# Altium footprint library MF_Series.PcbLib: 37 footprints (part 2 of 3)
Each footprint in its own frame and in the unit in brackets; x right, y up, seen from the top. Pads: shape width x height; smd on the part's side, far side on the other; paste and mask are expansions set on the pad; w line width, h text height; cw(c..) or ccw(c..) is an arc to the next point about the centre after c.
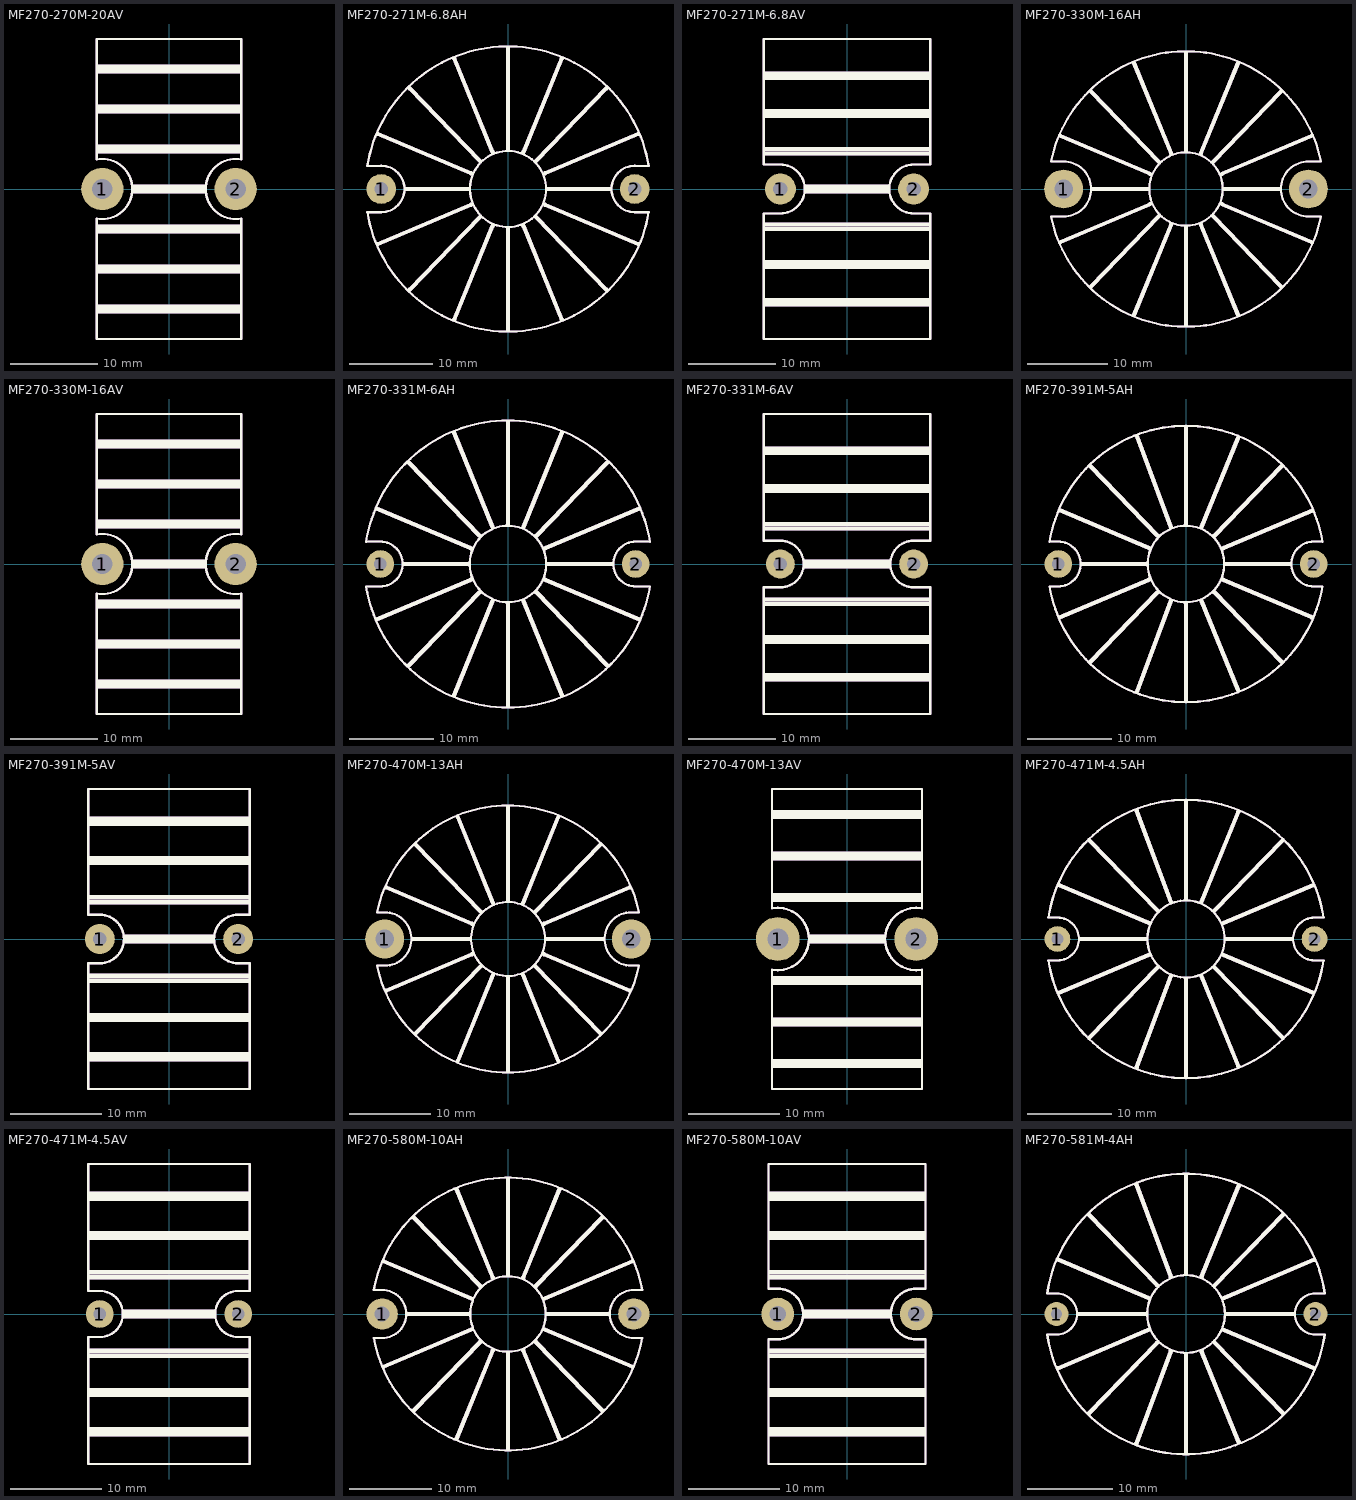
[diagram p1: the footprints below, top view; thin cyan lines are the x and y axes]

## MF270-270M-20AV [mil]
pads (2):
  round 190 hole 91: 1(-300,0) 2(300,0)
Top Overlay:
  lines w10: -325,-132.66 ccw(c-300,0) -325,132.66 ; -325,-132.27 -325,-675 325,-675 325,-132.27 ; -325,132.27 -325,675 325,675 325,132.27 ; 325,-132.66 cw(c300,0) 325,132.66
  lines w19.68: -320,-550 320,-550 ; -320,-530 320,-530 ; -320,-370 320,-370 ; -320,-350 320,-350 ; -320,-190 320,-190 ; -320,-170 320,-170 ; -320,170 320,170 ; -320,190 320,190 ; -320,350 320,350 ; -320,370 320,370 ; -320,530 320,530 ; -320,550 320,550 ; -160,-10 160,-10 ; -160,10 160,10
Mechanical 29:
  lines w10: -325,-132.66 ccw(c-300,0) -325,132.66 ; -325,-132.27 -325,-675 325,-675 325,-132.27 ; -325,132.27 -325,675 325,675 325,132.27 ; 325,-132.66 cw(c300,0) 325,132.66
  lines w19.68: -320,-550 320,-550 ; -320,-530 320,-530 ; -320,-370 320,-370 ; -320,-350 320,-350 ; -320,-190 320,-190 ; -320,-170 320,-170 ; -320,170 320,170 ; -320,190 320,190 ; -320,350 320,350 ; -320,370 320,370 ; -320,530 320,530 ; -320,550 320,550 ; -160,-10 160,-10 ; -160,10 160,10
  text "'.Designator'" at -1750,-64.83 h400

## MF270-271M-6.8AH [mil]
pads (2):
  round 140 hole 65: 1(-600,0) 2(600,0)
Top Overlay:
  circle w10: c0,0 r180
  lines w10: 666.04,109.62 ccw(c0,0) -666.02,109.73 -600,110 cw(c-600,0) -600,-110 -665.98,-110 ccw(c0,0) 665.98,-110 600,-110 cw(c600,0) 600,110 666.04,109.73
  lines w19.68: -617.26,-261.55 -175.3,-74.28 ; -617.26,261.55 -175.3,74.28 ; -485,0 -185,0 ; -466.61,-477.13 -132.5,-132.5 ; -466.61,477.13 -132.5,132.5 ; -254.48,-618.14 -72.46,-173.99 ; -254.48,618.14 -72.46,173.99 ; 0,-665 0,-185 ; 0,185 0,665 ; 72.46,-173.99 254.48,-618.14 ; 72.46,173.99 254.48,618.14 ; 132.5,-132.5 466.61,-477.13 ; 132.5,132.5 466.61,477.13 ; 175.3,-74.28 617.26,-261.55 ; 175.3,74.28 617.26,261.55 ; 185,0 485,0
Mechanical 29:
  circle w10: c0,0 r180
  lines w10: 666.04,109.62 ccw(c0,0) -666.02,109.73 -600,110 cw(c-600,0) -600,-110 -665.98,-110 ccw(c0,0) 665.98,-110 600,-110 cw(c600,0) 600,110 666.04,109.73
  lines w19.68: -617.26,-261.55 -175.3,-74.28 ; -617.26,261.55 -175.3,74.28 ; -485,0 -185,0 ; -466.61,-477.13 -132.5,-132.5 ; -466.61,477.13 -132.5,132.5 ; -254.48,-618.14 -72.46,-173.99 ; -254.48,618.14 -72.46,173.99 ; 0,-665 0,-185 ; 0,185 0,665 ; 72.46,-173.99 254.48,-618.14 ; 72.46,173.99 254.48,618.14 ; 132.5,-132.5 466.61,-477.13 ; 132.5,132.5 466.61,477.13 ; 175.3,-74.28 617.26,-261.55 ; 175.3,74.28 617.26,261.55 ; 185,0 485,0
  text "'.Designator'" at -290,145.17 h400

## MF270-271M-6.8AV [mil]
pads (2):
  round 140 hole 65: 1(-300,0) 2(300,0)
Top Overlay:
  lines w10: -375,-675 375,-675 375,-110 300,-110 cw(c300,0) 300,110 375,110 375,675 -375,675 -375,110 -300,110 cw(c-300,0) -300,-110 -375,-110 -375,-675
  lines w19.68: -370,-520 370,-520 ; -370,-500 370,-500 ; -370,-350 370,-350 ; -370,-330 370,-330 ; -370,-180 370,-180 ; -370,-160 370,-160 ; -370,160 370,160 ; -370,180 370,180 ; -370,330 370,330 ; -370,350 370,350 ; -370,500 370,500 ; -370,520 370,520 ; -185,-10 185,-10 ; -185,10 185,10
Mechanical 29:
  lines w10: -375,-675 375,-675 375,-110 300,-110 cw(c300,0) 300,110 375,110 375,675 -375,675 -375,110 -300,110 cw(c-300,0) -300,-110 -375,-110 -375,-675
  lines w19.68: -370,-520 370,-520 ; -370,-500 370,-500 ; -370,-350 370,-350 ; -370,-330 370,-330 ; -370,-180 370,-180 ; -370,-160 370,-160 ; -370,160 370,160 ; -370,180 370,180 ; -370,330 370,330 ; -370,350 370,350 ; -370,500 370,500 ; -370,520 370,520 ; -185,-10 185,-10 ; -185,10 185,10
  text "'.Designator'" at -1750,-64.83 h400

## MF270-330M-16AH [mil]
pads (2):
  round 190 hole 91: 1(-600,0) 2(600,0)
Top Overlay:
  circle w10: c0,0 r180
  lines w10: -661.36,-135 ccw(c0,0) 661.36,-135 600,-135 cw(c600,0) 600,135 661.36,135 ccw(c0,0) -661.36,135 -600,135 cw(c-600,0) -600,-135 -661.36,-135
  lines w19.68: -617.26,-261.55 -175.3,-74.28 ; -617.26,261.55 -175.3,74.28 ; -466.61,-477.13 -132.5,-132.5 ; -466.61,477.13 -132.5,132.5 ; -460,0 -185,0 ; -254.48,-618.14 -72.46,-173.99 ; -254.48,618.14 -72.46,173.99 ; 0,-665 0,-185 ; 0,185 0,665 ; 72.46,-173.99 254.48,-618.14 ; 72.46,173.99 254.48,618.14 ; 132.5,-132.5 466.61,-477.13 ; 132.5,132.5 466.61,477.13 ; 175.3,-74.28 617.26,-261.55 ; 175.3,74.28 617.26,261.55 ; 185,0 460,0
Mechanical 29:
  circle w10: c0,0 r180
  lines w10: -661.36,-135 ccw(c0,0) 661.36,-135 600,-135 cw(c600,0) 600,135 661.36,135 ccw(c0,0) -661.36,135 -600,135 cw(c-600,0) -600,-135 -661.36,-135
  lines w19.68: -617.26,-261.55 -175.3,-74.28 ; -617.26,261.55 -175.3,74.28 ; -466.61,-477.13 -132.5,-132.5 ; -466.61,477.13 -132.5,132.5 ; -460,0 -185,0 ; -254.48,-618.14 -72.46,-173.99 ; -254.48,618.14 -72.46,173.99 ; 0,-665 0,-185 ; 0,185 0,665 ; 72.46,-173.99 254.48,-618.14 ; 72.46,173.99 254.48,618.14 ; 132.5,-132.5 466.61,-477.13 ; 132.5,132.5 466.61,477.13 ; 175.3,-74.28 617.26,-261.55 ; 175.3,74.28 617.26,261.55 ; 185,0 460,0
  text "'.Designator'" at -290,145.17 h400

## MF270-330M-16AV [mil]
pads (2):
  round 190 hole 91: 1(-300,0) 2(300,0)
Top Overlay:
  lines w10: -325,-132.66 ccw(c-300,0) -325,132.66 ; -325,-132.27 -325,-675 325,-675 325,-132.27 ; -325,132.27 -325,675 325,675 325,132.27 ; 325,-132.66 cw(c300,0) 325,132.66
  lines w19.68: -320,-550 320,-550 ; -320,-530 320,-530 ; -320,-370 320,-370 ; -320,-350 320,-350 ; -320,-190 320,-190 ; -320,-170 320,-170 ; -320,170 320,170 ; -320,190 320,190 ; -320,350 320,350 ; -320,370 320,370 ; -320,530 320,530 ; -320,550 320,550 ; -160,-10 160,-10 ; -160,10 160,10
Mechanical 29:
  lines w10: -325,-132.66 ccw(c-300,0) -325,132.66 ; -325,-132.27 -325,-675 325,-675 325,-132.27 ; -325,132.27 -325,675 325,675 325,132.27 ; 325,-132.66 cw(c300,0) 325,132.66
  lines w19.68: -320,-550 320,-550 ; -320,-530 320,-530 ; -320,-370 320,-370 ; -320,-350 320,-350 ; -320,-190 320,-190 ; -320,-170 320,-170 ; -320,170 320,170 ; -320,190 320,190 ; -320,350 320,350 ; -320,370 320,370 ; -320,530 320,530 ; -320,550 320,550 ; -160,-10 160,-10 ; -160,10 160,10
  text "'.Designator'" at -1750,-64.83 h400

## MF270-331M-6AH [mil]
pads (2):
  round 130 hole 60: 1(-600,0) 2(600,0)
Top Overlay:
  circle w10: c0,0 r180
  lines w10: -666.81,104.84 cw(c0,0) 666.82,104.75 ; -666.77,-105.1 ccw(c0,0) 666.78,-105.02 ; -666.13,-105 -600,-105 ccw(c-600,0) -600,105 -666.15,104.73 ; 666.67,-105 600,-105 cw(c600,0) 600,105 666.7,104.73
  lines w19.68: -617.26,-261.55 -175.3,-74.28 ; -617.26,261.55 -175.3,74.28 ; -490,0 -185,0 ; -466.61,-477.13 -132.5,-132.5 ; -466.61,477.13 -132.5,132.5 ; -254.48,-618.14 -72.46,-173.99 ; -254.48,618.14 -72.46,173.99 ; 0,-665 0,-185 ; 0,185 0,665 ; 72.46,-173.99 254.48,-618.14 ; 72.46,173.99 254.48,618.14 ; 132.5,-132.5 466.61,-477.13 ; 132.5,132.5 466.61,477.13 ; 175.3,-74.28 617.26,-261.55 ; 175.3,74.28 617.26,261.55 ; 185,0 490,0
Mechanical 29:
  circle w10: c0,0 r180
  lines w10: -666.81,104.84 cw(c0,0) 666.82,104.75 ; -666.77,-105.1 ccw(c0,0) 666.78,-105.02 ; -666.13,-105 -600,-105 ccw(c-600,0) -600,105 -666.15,104.73 ; 666.67,-105 600,-105 cw(c600,0) 600,105 666.7,104.73
  lines w19.68: -617.26,-261.55 -175.3,-74.28 ; -617.26,261.55 -175.3,74.28 ; -490,0 -185,0 ; -466.61,-477.13 -132.5,-132.5 ; -466.61,477.13 -132.5,132.5 ; -254.48,-618.14 -72.46,-173.99 ; -254.48,618.14 -72.46,173.99 ; 0,-665 0,-185 ; 0,185 0,665 ; 72.46,-173.99 254.48,-618.14 ; 72.46,173.99 254.48,618.14 ; 132.5,-132.5 466.61,-477.13 ; 132.5,132.5 466.61,477.13 ; 175.3,-74.28 617.26,-261.55 ; 175.3,74.28 617.26,261.55 ; 185,0 490,0
  text "'.Designator'" at -290,145.17 h400

## MF270-331M-6AV [mil]
pads (2):
  round 130 hole 60: 1(-300,0) 2(300,0)
Top Overlay:
  lines w10: -375,-675 375,-675 375,-105 300,-105 cw(c300,0) 300,105 375,105 375,675 -375,675 -375,105 -300,105 cw(c-300,0) -300,-105 -375,-105 -375,-675
  lines w19.68: -370,-520 370,-520 ; -370,-500 370,-500 ; -370,-350 370,-350 ; -370,-330 370,-330 ; -370,-180 370,-180 ; -370,-160 370,-160 ; -370,160 370,160 ; -370,180 370,180 ; -370,330 370,330 ; -370,350 370,350 ; -370,500 370,500 ; -370,520 370,520 ; -190,-10 190,-10 ; -190,10 190,10
Mechanical 29:
  lines w10: -375,-675 375,-675 375,-105 300,-105 cw(c300,0) 300,105 375,105 375,675 -375,675 -375,105 -300,105 cw(c-300,0) -300,-105 -375,-105 -375,-675
  lines w19.68: -370,-520 370,-520 ; -370,-500 370,-500 ; -370,-350 370,-350 ; -370,-330 370,-330 ; -370,-180 370,-180 ; -370,-160 370,-160 ; -370,160 370,160 ; -370,180 370,180 ; -370,330 370,330 ; -370,350 370,350 ; -370,500 370,500 ; -370,520 370,520 ; -190,-10 190,-10 ; -190,10 190,10
  text "'.Designator'" at -1750,-64.83 h400

## MF270-391M-5AH [mil]
pads (2):
  round 130 hole 60: 1(-600,0) 2(600,0)
Top Overlay:
  circle w10: c0,0 r180
  lines w10: -641.49,104.83 cw(c0,0) 641.49,104.83 600,105 ccw(c600,0) 600,-105 641.46,-105 cw(c0,0) -641.46,-105 -600,-105 ccw(c-600,0) -600,105 -641.49,104.83
  lines w19.68: -594.24,-251.8 -175.3,-74.28 ; -593.79,252.95 -173.05,74.68 ; -490,0 -185,0 ; -450,-460 -132.7,-132.43 ; -450,460 -132.7,132.43 ; -230,-600 -70.44,-171.87 ; -230,600 -70.44,171.87 ; 0,-640 0,-185 ; 0,185 0,640 ; 72.46,-173.99 243.97,-592.47 ; 72.46,173.99 243.97,592.47 ; 132.5,-132.5 450,-460 ; 132.5,132.5 450,460 ; 175.3,-74.28 590,-250 ; 175.3,74.28 594.24,251.8 ; 185,0 490,0
Mechanical 29:
  circle w10: c0,0 r180
  lines w10: -641.49,104.83 cw(c0,0) 641.49,104.83 600,105 ccw(c600,0) 600,-105 641.46,-105 cw(c0,0) -641.46,-105 -600,-105 ccw(c-600,0) -600,105 -641.49,104.83
  lines w19.68: -594.24,-251.8 -175.3,-74.28 ; -593.79,252.95 -173.05,74.68 ; -490,0 -185,0 ; -450,-460 -132.7,-132.43 ; -450,460 -132.7,132.43 ; -230,-600 -70.44,-171.87 ; -230,600 -70.44,171.87 ; 0,-640 0,-185 ; 0,185 0,640 ; 72.46,-173.99 243.97,-592.47 ; 72.46,173.99 243.97,592.47 ; 132.5,-132.5 450,-460 ; 132.5,132.5 450,460 ; 175.3,-74.28 590,-250 ; 175.3,74.28 594.24,251.8 ; 185,0 490,0
  text "'.Designator'" at -290,145.17 h400

## MF270-391M-5AV [mil]
pads (2):
  round 130 hole 60: 1(-300,0) 2(300,0)
Top Overlay:
  lines w10: -350,-650 -350,-105 -300,-105 ccw(c-300,0) -300,105 -350,105 -350,650 350,650 350,105 300,105 ccw(c300,0) 300,-105 350,-105 350,-650 -350,-650
  lines w19.68: -345,-520 345,-520 ; -345,-500 345,-500 ; -345,-350 345,-350 ; -345,-330 345,-330 ; -345,-180 345,-180 ; -345,-160 345,-160 ; -345,160 345,160 ; -345,180 345,180 ; -345,330 345,330 ; -345,350 345,350 ; -345,500 345,500 ; -345,520 345,520 ; -190,-10 190,-10 ; -190,10 190,10
Mechanical 29:
  lines w10: -350,-650 -350,-105 -300,-105 ccw(c-300,0) -300,105 -350,105 -350,650 350,650 350,105 300,105 ccw(c300,0) 300,-105 350,-105 350,-650 -350,-650
  lines w19.68: -345,-520 345,-520 ; -345,-500 345,-500 ; -345,-350 345,-350 ; -345,-330 345,-330 ; -345,-180 345,-180 ; -345,-160 345,-160 ; -345,160 345,160 ; -345,180 345,180 ; -345,330 345,330 ; -345,350 345,350 ; -345,500 345,500 ; -345,520 345,520 ; -190,-10 190,-10 ; -190,10 190,10
  text "'.Designator'" at -1750,-64.83 h400

## MF270-470M-13AH [mil]
pads (2):
  round 190 hole 91: 1(-600,0) 2(600,0)
Top Overlay:
  circle w10: c0,0 r180
  lines w10: -636.85,-130.09 ccw(c0,0) 636.85,-130.09 ; -636.85,130.09 cw(c0,0) 636.79,130.37 ; -636.43,-130 -600,-130 ccw(c-600,0) -600,130 -636.43,130 ; 636.43,-130 600,-130 cw(c600,0) 600,130 636.43,130
  lines w19.68: -594.25,-251.8 -175.3,-74.28 ; -594.25,251.8 -175.3,74.28 ; -465,0 -185,0 ; -449.21,-459.18 -132.5,-132.5 ; -449.21,459.18 -132.5,132.5 ; -245,-595.01 -72.46,-173.99 ; -245,595.01 -72.46,173.99 ; 0,-645 0,-185 ; 0,185 0,645 ; 72.46,-173.99 245,-595.01 ; 72.46,173.99 245,595.01 ; 132.5,-132.5 449.21,-459.18 ; 132.5,132.5 449.21,459.18 ; 175.3,-74.28 594.25,-251.8 ; 175.3,74.28 594.25,251.8 ; 185,0 465,0
Mechanical 29:
  circle w10: c0,0 r180
  lines w10: -636.85,-130.09 ccw(c0,0) 636.85,-130.09 ; -636.85,130.09 cw(c0,0) 636.79,130.37 ; -636.43,-130 -600,-130 ccw(c-600,0) -600,130 -636.43,130 ; 636.43,-130 600,-130 cw(c600,0) 600,130 636.43,130
  lines w19.68: -594.25,-251.8 -175.3,-74.28 ; -594.25,251.8 -175.3,74.28 ; -465,0 -185,0 ; -449.21,-459.18 -132.5,-132.5 ; -449.21,459.18 -132.5,132.5 ; -245,-595.01 -72.46,-173.99 ; -245,595.01 -72.46,173.99 ; 0,-645 0,-185 ; 0,185 0,645 ; 72.46,-173.99 245,-595.01 ; 72.46,173.99 245,595.01 ; 132.5,-132.5 449.21,-459.18 ; 132.5,132.5 449.21,459.18 ; 175.3,-74.28 594.25,-251.8 ; 175.3,74.28 594.25,251.8 ; 185,0 465,0
  text "'.Designator'" at -290,145.17 h400

## MF270-470M-13AV [mil]
pads (2):
  round 190 hole 91: 1(-300,0) 2(300,0)
Top Overlay:
  lines w10: -325,-132.66 ccw(c-300,0) -325,132.66 ; -325,-132.27 -325,-650 325,-650 325,-132.27 ; -325,132.27 -325,650 325,650 325,132.27 ; 325,-132.66 cw(c300,0) 325,132.66
  lines w19.68: -320,-550 320,-550 ; -320,-530 320,-530 ; -320,-370 320,-370 ; -320,-350 320,-350 ; -320,-190 320,-190 ; -320,-170 320,-170 ; -320,170 320,170 ; -320,190 320,190 ; -320,350 320,350 ; -320,370 320,370 ; -320,530 320,530 ; -320,550 320,550 ; -160,-10 160,-10 ; -160,10 160,10
Mechanical 29:
  lines w10: -325,-132.66 ccw(c-300,0) -325,132.66 ; -325,-132.27 -325,-650 325,-650 325,-132.27 ; -325,132.27 -325,650 325,650 325,132.27 ; 325,-132.66 cw(c300,0) 325,132.66
  lines w19.68: -320,-550 320,-550 ; -320,-530 320,-530 ; -320,-370 320,-370 ; -320,-350 320,-350 ; -320,-190 320,-190 ; -320,-170 320,-170 ; -320,170 320,170 ; -320,190 320,190 ; -320,350 320,350 ; -320,370 320,370 ; -320,530 320,530 ; -320,550 320,550 ; -160,-10 160,-10 ; -160,10 160,10
  text "'.Designator'" at -1750,-64.83 h400

## MF270-471M-4.5AH [mil]
pads (2):
  round 120 hole 55: 1(-600,0) 2(600,0)
Top Overlay:
  circle w10: c0,0 r180
  lines w10: -642.52,-100 -600,-100 ccw(c-600,0) -600,100 -642.52,100 ; -642.26,-100 ccw(c0,0) 642.27,-99.96 ; -642.26,100 cw(c0,0) 642.27,99.96 ; 642.52,-100 600,-100 cw(c600,0) 600,100 642.52,100
  lines w19.68: -594.24,-251.8 -175.3,-74.28 ; -593.79,252.95 -173.05,74.68 ; -495,0 -185,0 ; -450,-460 -132.7,-132.43 ; -450,460 -132.7,132.43 ; -230,-600 -70.44,-171.87 ; -230,600 -70.44,171.87 ; 0,-640 0,-185 ; 0,185 0,640 ; 72.46,-173.99 243.97,-592.47 ; 72.46,173.99 243.97,592.47 ; 132.5,-132.5 450,-460 ; 132.5,132.5 450,460 ; 175.3,-74.28 590,-250 ; 175.3,74.28 594.24,251.8 ; 185,0 495,0
Mechanical 29:
  circle w10: c0,0 r180
  lines w10: -642.52,-100 -600,-100 ccw(c-600,0) -600,100 -642.52,100 ; -642.26,-100 ccw(c0,0) 642.27,-99.96 ; -642.26,100 cw(c0,0) 642.27,99.96 ; 642.52,-100 600,-100 cw(c600,0) 600,100 642.52,100
  lines w19.68: -594.24,-251.8 -175.3,-74.28 ; -593.79,252.95 -173.05,74.68 ; -495,0 -185,0 ; -450,-460 -132.7,-132.43 ; -450,460 -132.7,132.43 ; -230,-600 -70.44,-171.87 ; -230,600 -70.44,171.87 ; 0,-640 0,-185 ; 0,185 0,640 ; 72.46,-173.99 243.97,-592.47 ; 72.46,173.99 243.97,592.47 ; 132.5,-132.5 450,-460 ; 132.5,132.5 450,460 ; 175.3,-74.28 590,-250 ; 175.3,74.28 594.24,251.8 ; 185,0 495,0
  text "'.Designator'" at -290,145.17 h400

## MF270-471M-4.5AV [mil]
pads (2):
  round 120 hole 55: 1(-300,0) 2(300,0)
Top Overlay:
  lines w10: -350,-650 -350,-100 -300,-100 ccw(c-300,0) -300,100 -350,100 -350,650 350,650 350,100 300,100 ccw(c300,0) 300,-100 350,-100 350,-650 -350,-650
  lines w19.68: -345,-520 345,-520 ; -345,-500 345,-500 ; -345,-350 345,-350 ; -345,-330 345,-330 ; -345,-180 345,-180 ; -345,-160 345,-160 ; -345,160 345,160 ; -345,180 345,180 ; -345,330 345,330 ; -345,350 345,350 ; -345,500 345,500 ; -345,520 345,520 ; -195,-10 195,-10 ; -195,10 195,10
Mechanical 29:
  lines w10: -350,-650 -350,-100 -300,-100 ccw(c-300,0) -300,100 -350,100 -350,650 350,650 350,100 300,100 ccw(c300,0) 300,-100 350,-100 350,-650 -350,-650
  lines w19.68: -345,-520 345,-520 ; -345,-500 345,-500 ; -345,-350 345,-350 ; -345,-330 345,-330 ; -345,-180 345,-180 ; -345,-160 345,-160 ; -345,160 345,160 ; -345,180 345,180 ; -345,330 345,330 ; -345,350 345,350 ; -345,500 345,500 ; -345,520 345,520 ; -195,-10 195,-10 ; -195,10 195,10
  text "'.Designator'" at -1750,-64.83 h400

## MF270-580M-10AH [mil]
pads (2):
  round 150 hole 71: 1(-600,0) 2(600,0)
Top Overlay:
  circle w10: c0,0 r180
  lines w10: -639.75,-115 ccw(c0,0) 639.75,-115 600,-115 cw(c600,0) 600,115 639.77,114.84 ccw(c0,0) -639.77,114.84 -600,115 cw(c-600,0) -600,-115 -639.75,-115
  lines w19.68: -594.25,-251.8 -175.3,-74.28 ; -594.25,251.8 -175.3,74.28 ; -480,0 -185,0 ; -449.21,-459.18 -132.5,-132.5 ; -449.21,459.18 -132.5,132.5 ; -245,-595.01 -72.46,-173.99 ; -245,595.01 -72.46,173.99 ; 0,-645 0,-185 ; 0,185 0,645 ; 72.46,-173.99 245,-595.01 ; 72.46,173.99 245,595.01 ; 132.5,-132.5 449.21,-459.18 ; 132.5,132.5 449.21,459.18 ; 175.3,-74.28 594.25,-251.8 ; 175.3,74.28 594.25,251.8 ; 185,0 480,0
Mechanical 29:
  circle w10: c0,0 r180
  lines w10: -639.75,-115 ccw(c0,0) 639.75,-115 600,-115 cw(c600,0) 600,115 639.77,114.84 ccw(c0,0) -639.77,114.84 -600,115 cw(c-600,0) -600,-115 -639.75,-115
  lines w19.68: -594.25,-251.8 -175.3,-74.28 ; -594.25,251.8 -175.3,74.28 ; -480,0 -185,0 ; -449.21,-459.18 -132.5,-132.5 ; -449.21,459.18 -132.5,132.5 ; -245,-595.01 -72.46,-173.99 ; -245,595.01 -72.46,173.99 ; 0,-645 0,-185 ; 0,185 0,645 ; 72.46,-173.99 245,-595.01 ; 72.46,173.99 245,595.01 ; 132.5,-132.5 449.21,-459.18 ; 132.5,132.5 449.21,459.18 ; 175.3,-74.28 594.25,-251.8 ; 175.3,74.28 594.25,251.8 ; 185,0 480,0
  text "'.Designator'" at -290,145.17 h400

## MF270-580M-10AV [mil]
pads (2):
  round 142 hole 71: 1(-300,0) 2(300,0)
Top Overlay:
  lines w10: -340,-650 -340,-110 -300,-110 ccw(c-300,0) -300,110 -340,110 -340,650 340,650 340,110 300,110 ccw(c300,0) 300,-110 340,-110 340,-650 -340,-650
  lines w19.68: -335,-520 335,-520 ; -335,-500 335,-500 ; -335,-350 335,-350 ; -335,-330 335,-330 ; -335,-180 335,-180 ; -335,-160 335,-160 ; -335,160 335,160 ; -335,180 335,180 ; -335,330 335,330 ; -335,350 335,350 ; -335,500 335,500 ; -335,520 335,520 ; -185,-10 185,-10 ; -185,10 185,10
Mechanical 29:
  lines w10: -340,-650 -340,-110 -300,-110 ccw(c-300,0) -300,110 -340,110 -340,650 340,650 340,110 300,110 ccw(c300,0) 300,-110 340,-110 340,-650 -340,-650
  lines w19.68: -335,-520 335,-520 ; -335,-500 335,-500 ; -335,-350 335,-350 ; -335,-330 335,-330 ; -335,-180 335,-180 ; -335,-160 335,-160 ; -335,160 335,160 ; -335,180 335,180 ; -335,330 335,330 ; -335,350 335,350 ; -335,500 335,500 ; -335,520 335,520 ; -185,-10 185,-10 ; -185,10 185,10
  text "'.Designator'" at -1750,-64.83 h400

## MF270-581M-4AH [mil]
pads (2):
  round 110 hole 51: 1(-600,0) 2(600,0)
Top Overlay:
  circle w10: c0,0 r180
  lines w10: -643.01,-95.07 ccw(c0,0) 643.06,-94.71 ; -643.01,95.07 cw(c0,0) 642.96,95.44 ; -642.52,-95 -600,-95 ccw(c-600,0) -600,95 -642.52,95 ; 642.52,-95 600,-95 cw(c600,0) 600,95 642.52,95
  lines w19.68: -594.24,-251.8 -175.3,-74.28 ; -593.79,252.95 -173.05,74.68 ; -500,0 -185,0 ; -450,-460 -132.7,-132.43 ; -450,460 -132.7,132.43 ; -230,-600 -70.44,-171.87 ; -230,600 -70.44,171.87 ; 0,-640 0,-185 ; 0,185 0,640 ; 72.46,-173.99 243.97,-592.47 ; 72.46,173.99 243.97,592.47 ; 132.5,-132.5 450,-460 ; 132.5,132.5 450,460 ; 175.3,-74.28 590,-250 ; 175.3,74.28 594.24,251.8 ; 185,0 500,0
Mechanical 29:
  circle w10: c0,0 r180
  lines w10: -643.01,-95.07 ccw(c0,0) 643.06,-94.71 ; -643.01,95.07 cw(c0,0) 642.96,95.44 ; -642.52,-95 -600,-95 ccw(c-600,0) -600,95 -642.52,95 ; 642.52,-95 600,-95 cw(c600,0) 600,95 642.52,95
  lines w19.68: -594.24,-251.8 -175.3,-74.28 ; -593.79,252.95 -173.05,74.68 ; -500,0 -185,0 ; -450,-460 -132.7,-132.43 ; -450,460 -132.7,132.43 ; -230,-600 -70.44,-171.87 ; -230,600 -70.44,171.87 ; 0,-640 0,-185 ; 0,185 0,640 ; 72.46,-173.99 243.97,-592.47 ; 72.46,173.99 243.97,592.47 ; 132.5,-132.5 450,-460 ; 132.5,132.5 450,460 ; 175.3,-74.28 590,-250 ; 175.3,74.28 594.24,251.8 ; 185,0 500,0
  text "'.Designator'" at -290,145.17 h400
